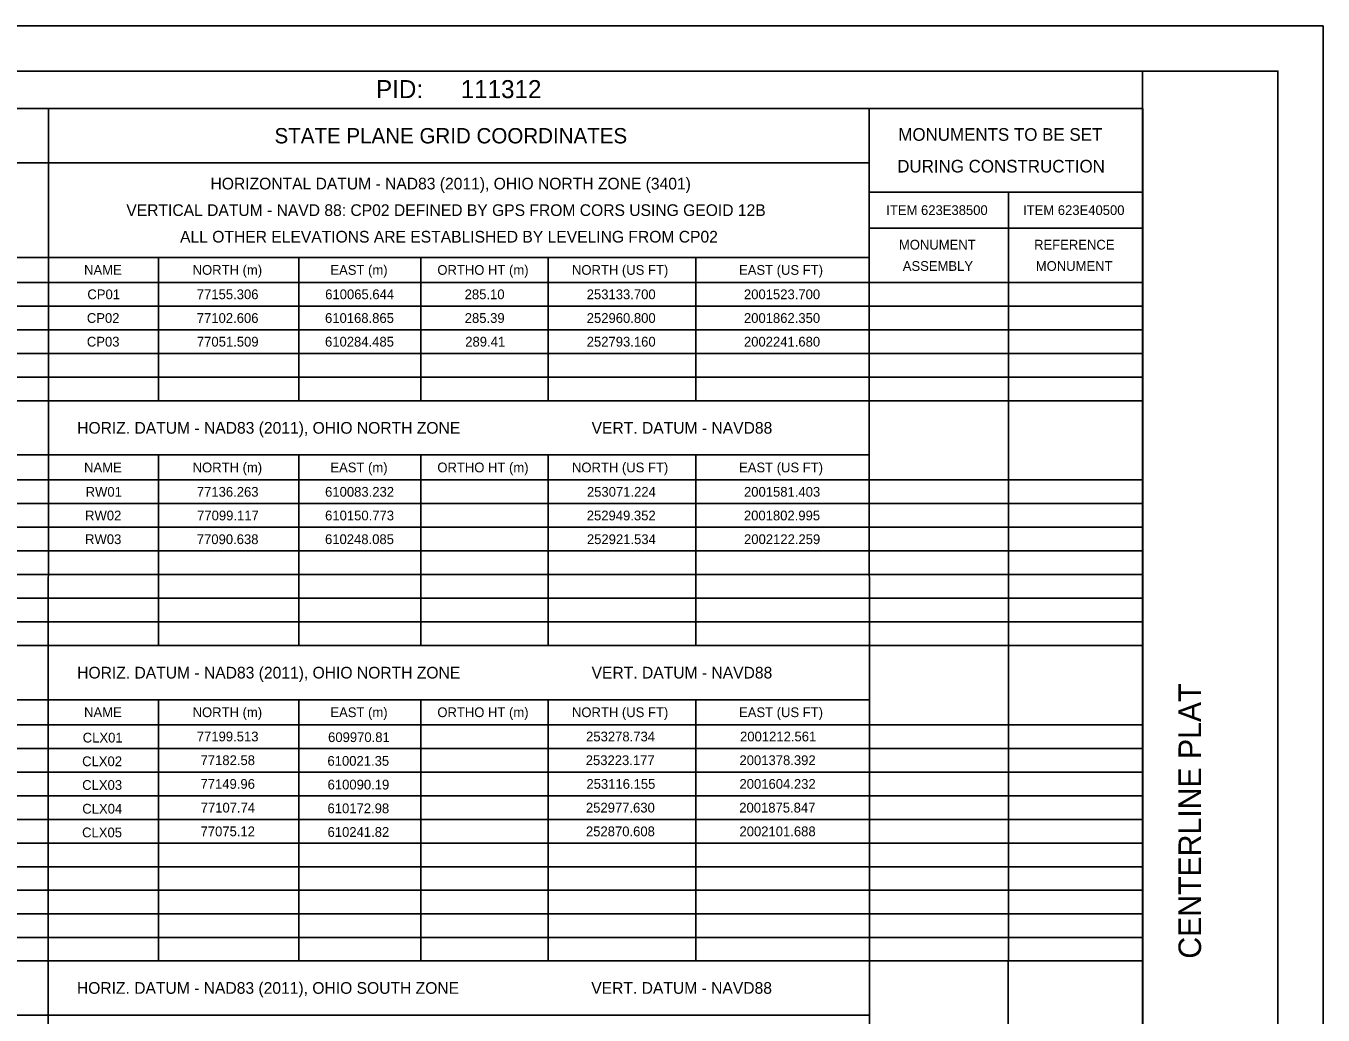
# Model space of a CAD drawing. Extents: x -4451 to 6119, y -1533 to 848.
# Drawn here: x 392.9 to 680, y 221 to 440 of the extents above; entities that cross this region are included whole.
import ezdxf

# ---------------------------------------------------------------- set-up
doc = ezdxf.new("R2010")
doc.units = 0
for name, color, linetype in [('SC_Scratch1', 7, 'Continuous'), ('SH_Border', 7, 'Continuous'), ('SH_Cut_Line', 7, 'Continuous'), ('SH_Data', 7, 'Continuous')]:
    doc.layers.add(name, color=color, linetype=linetype)

msp = doc.modelspace()

# ---------------------------------------------------------------- linework, layer by layer
at = {"layer": 'SC_Scratch1'}
for p, q in [((30.12, 421.7), (640.12, 421.7)), ((397.78, 44.46), (397.85, 421.7)), ((579.71, 44.38), (579.55, 421.7)), ((640.12, 74.32), (640.12, 421.7)), ((246.43, 409.69), (397.85, 409.69)), ((397.85, 409.69), (579.55, 409.69)), ((579.55, 403.22), (640.12, 403.22)), ((610.38, 357.03), (610.38, 403.22)), ((579.55, 395.21), (640.12, 395.21)), ((30.12, 388.75), (579.55, 388.75)), ((422.19, 357.03), (422.19, 388.75)), ((453.28, 357.03), (453.28, 388.75)), ((480.32, 357.03), (480.32, 388.75)), ((508.44, 357.03), (508.44, 388.75)), ((541.16, 357.03), (541.16, 388.75)), ((246.43, 383.2), (640.12, 383.2)), ((30.12, 377.97), (640.12, 377.97)), ((30.12, 372.73), (640.12, 372.73)), ((30.12, 367.5), (640.12, 367.5)), ((30.12, 362.26), (640.12, 362.26)), ((30.12, 357.03), (640.12, 357.03)), ((610.38, 313.31), (610.38, 357.03)), ((30.12, 345.02), (579.55, 345.02)), ((422.19, 302.78), (422.19, 345.02)), ((453.28, 302.81), (453.28, 345.02)), ((480.32, 302.83), (480.32, 345.02)), ((508.44, 302.8), (508.44, 345.02)), ((541.16, 302.8), (541.16, 345.02)), ((30.12, 339.47), (640.12, 339.47)), ((30.12, 334.24), (640.12, 334.24)), ((30.12, 329), (640.12, 329)), ((30.12, 323.77), (640.12, 323.77)), ((30.12, 318.53), (640.12, 318.53)), ((30.12, 313.3), (640.12, 313.3)), ((610.38, 269.59), (610.38, 313.31)), ((610.38, 250.5), (610.38, 313.31)), ((30.12, 308.06), (640.12, 308.06)), ((30.12, 302.83), (640.12, 302.83)), ((30.12, 302.83), (640.12, 302.83)), ((610.38, 259.11), (610.38, 302.83)), ((30.12, 290.82), (579.55, 290.82)), ((422.19, 232.96), (422.19, 290.82)), ((453.28, 232.96), (453.28, 290.82)), ((480.32, 233.05), (480.32, 290.82)), ((508.44, 233.05), (508.44, 290.82)), ((541.16, 232.96), (541.16, 290.82)), ((30.12, 285.27), (640.12, 285.27)), ((30.12, 280.04), (640.12, 280.04)), ((30.12, 274.8), (640.12, 274.8)), ((30.12, 269.57), (640.12, 269.57)), ((30.12, 264.33), (640.12, 264.33)), ((30.12, 259.1), (640.12, 259.1)), ((610.38, 232.91), (610.38, 259.11)), ((30.12, 253.86), (640.12, 253.86)), ((30.12, 248.63), (640.12, 248.63)), ((30.12, 243.39), (640.12, 243.39)), ((30.12, 238.16), (640.12, 238.16)), ((30.05, 233.02), (640.05, 233.02)), ((30.05, 233.02), (640.05, 233.02)), ((30.05, 233.02), (640.05, 233.02)), ((610.31, 189.3), (610.31, 233.02)), ((30.05, 221.01), (579.48, 221.01))]:
    msp.add_line(p, q, dxfattribs=at)
at = {"layer": 'SH_Cut_Line'}
msp.add_lwpolyline([(0, 0), (680, 0), (680, 440), (0, 440)], close=True, dxfattribs=at)
at = {"layer": 'SH_Data'}
msp.add_line((640, 10), (640, 430), dxfattribs=at)
msp.add_lwpolyline([(30, 430), (670, 430), (670, 10), (30, 10)], close=True, dxfattribs=at)

# ---------------------------------------------------------------- texts
at = {"layer": 'SC_Scratch1'}
for s, height, p in [('PID:', 4, (470.38, 424.01)), ('111312', 4, (489.13, 424.01)), ('STATE PLANE GRID COORDINATES', 3.4, (447.9, 413.99)), ('MONUMENTS TO BE SET', 2.8, (585.99, 414.57)), ('DURING CONSTRUCTION', 2.8, (585.74, 407.55)), ('HORIZONTAL DATUM - NAD83 (2011), OHIO NORTH ZONE (3401)', 2.5878, (433.73, 403.8)), ('VERTICAL DATUM - NAVD 88: CP02 DEFINED BY GPS FROM CORS USING GEOID 12B', 2.5878, (415.1, 397.92)), ('ITEM 623E38500', 2.1565, (583.32, 398.14)), ('ITEM 623E40500', 2.1565, (613.6, 398.14)), ('ALL OTHER ELEVATIONS ARE ESTABLISHED BY LEVELING FROM CP02', 2.5878, (427, 392.04)), ('MONUMENT ', 2.157, (586.12, 390.49)), ('REFERENCE', 2.157, (616.04, 390.49)), ('ASSEMBLY', 2.157, (586.97, 385.77)), ('MONUMENT', 2.157, (616.41, 385.77)), ('NAME', 2.157, (405.75, 384.9)), ('NORTH (m)', 2.157, (429.78, 384.9)), ('EAST (m)', 2.157, (460.27, 384.9)), ('ORTHO HT (m)', 2.1565, (483.95, 384.9)), ('NORTH (US FT)', 2.1565, (513.75, 384.9)), ('EAST (US FT)', 2.1565, (550.73, 384.9)), ('CP01', 2.16, (406.48, 379.5)), ('77155.306', 2.16, (430.7, 379.5)), ('610065.644', 2.16, (459.12, 379.5)), ('285.10', 2.16, (489.99, 379.5)), ('253133.700', 2.16, (517.01, 379.5)), ('2001523.700', 2.16, (551.81, 379.5)), ('CP02', 2.16, (406.36, 374.25)), ('77102.606', 2.16, (430.7, 374.25)), ('610168.865', 2.16, (459.08, 374.25)), ('285.39', 2.16, (490.01, 374.25)), ('252960.800', 2.16, (517.01, 374.25)), ('2001862.350', 2.16, (551.81, 374.25)), ('CP03', 2.16, (406.36, 369.01)), ('77051.509', 2.16, (430.72, 369.01)), ('610284.485', 2.16, (459.08, 369.01)), ('289.41', 2.16, (490.12, 369.01)), ('252793.160', 2.16, (517.01, 369.01)), ('2002241.680', 2.16, (551.81, 369.01)), ('HORIZ. DATUM - NAD83 (2011), OHIO NORTH ZONE', 2.5878, (404.22, 349.72)), ('VERT. DATUM - NAVD88', 2.5878, (518.09, 349.72)), ('NAME', 2.157, (405.75, 341.17)), ('NORTH (m)', 2.157, (429.78, 341.17)), ('EAST (m)', 2.157, (460.27, 341.17)), ('ORTHO HT (m)', 2.1565, (483.95, 341.17)), ('NORTH (US FT)', 2.1565, (513.75, 341.17)), ('EAST (US FT)', 2.1565, (550.73, 341.17)), ('RW01', 2.16, (406.09, 335.77)), ('77136.263', 2.16, (430.71, 335.77)), ('610083.232', 2.16, (459.1, 335.77)), ('253071.224', 2.16, (517.05, 335.77)), ('2001581.403', 2.16, (551.82, 335.77)), ('RW02', 2.16, (405.97, 330.53)), ('77099.117', 2.16, (430.77, 330.53)), ('610150.773', 2.16, (459.1, 330.53)), ('252949.352', 2.16, (517.02, 330.53)), ('2001802.995', 2.16, (551.8, 330.53)), ('RW03', 2.16, (405.97, 325.28)), ('77090.638', 2.16, (430.7, 325.28)), ('610248.085', 2.16, (459.08, 325.28)), ('252921.534', 2.16, (517.05, 325.28)), ('2002122.259', 2.16, (551.83, 325.28)), ('HORIZ. DATUM - NAD83 (2011), OHIO NORTH ZONE', 2.5878, (404.22, 295.52)), ('VERT. DATUM - NAVD88', 2.5878, (518.09, 295.52)), ('NAME', 2.157, (405.75, 286.97)), ('NORTH (m)', 2.157, (429.78, 286.97)), ('EAST (m)', 2.157, (460.27, 286.97)), ('ORTHO HT (m)', 2.1565, (483.95, 286.97)), ('NORTH (US FT)', 2.1565, (513.75, 286.97)), ('EAST (US FT)', 2.1565, (550.73, 286.97)), ('CLX01', 2.16, (405.45, 281.35)), ('77199.513', 2.16, (430.7, 281.6)), ('609970.81', 2.16, (459.76, 281.45)), ('253278.734', 2.16, (516.87, 281.6)), ('2001212.561', 2.16, (550.95, 281.6)), ('77182.58', 2.16, (431.53, 276.35)), ('253223.177', 2.16, (516.79, 276.35)), ('2001378.392', 2.16, (550.82, 276.35)), ('CLX02', 2.16, (405.32, 276.11)), ('610021.35', 2.16, (459.62, 276.2)), ('CLX03', 2.16, (405.33, 270.86)), ('77149.96', 2.16, (431.52, 271.1)), ('610090.19', 2.16, (459.65, 270.95)), ('253116.155', 2.16, (516.94, 271.1)), ('2001604.232', 2.16, (550.82, 271.1)), ('CLX04', 2.16, (405.35, 265.61)), ('77107.74', 2.16, (431.56, 265.85)), ('610172.98', 2.16, (459.63, 265.7)), ('252977.630', 2.16, (516.83, 265.85)), ('2001875.847', 2.16, (550.77, 265.85)), ('CLX05', 2.16, (405.31, 260.36)), ('77075.12', 2.16, (431.53, 260.6)), ('610241.82', 2.16, (459.64, 260.46)), ('252870.608', 2.16, (516.84, 260.6)), ('2002101.688', 2.16, (550.82, 260.6)), ('HORIZ. DATUM - NAD83 (2011), OHIO SOUTH ZONE', 2.5878, (404.16, 225.71)), ('VERT. DATUM - NAVD88', 2.5878, (518.02, 225.71))]:
    msp.add_text(s, height=height, dxfattribs=at).set_placement(p)
at = {"layer": 'SH_Border'}
msp.add_text('CENTERLINE PLAT', height=5, rotation=90, dxfattribs=at).set_placement((653, 233.49))

doc.saveas('drawing.dxf')
